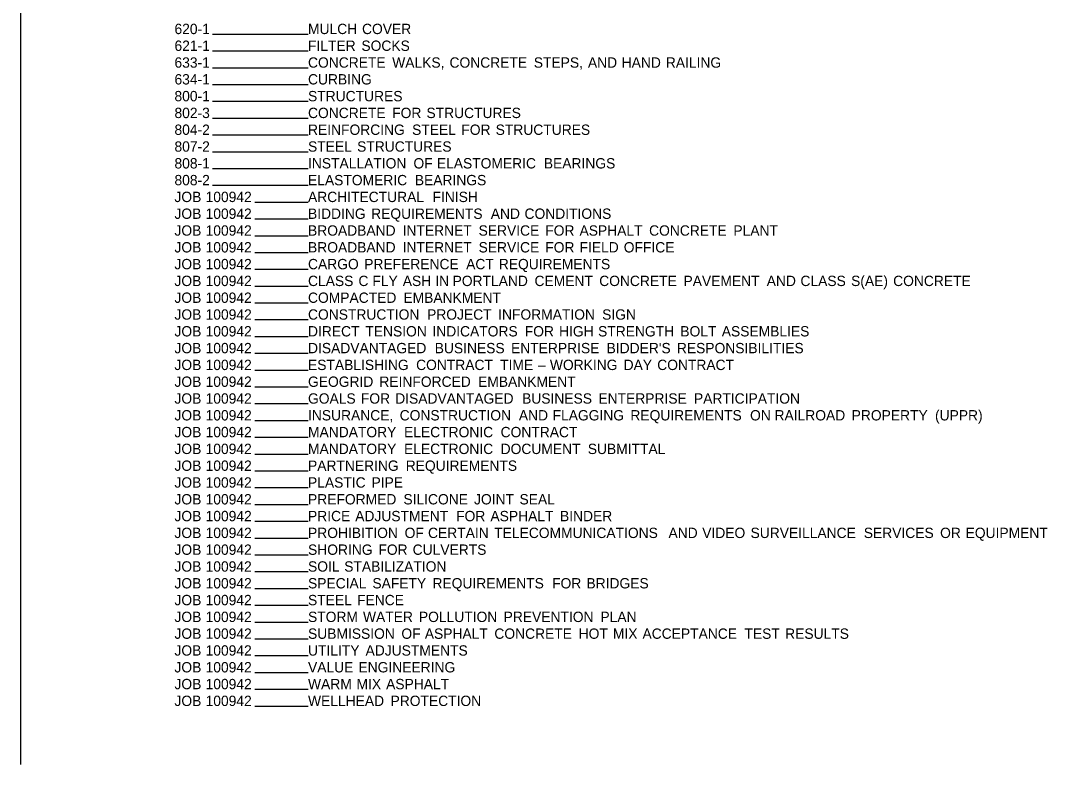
# Model space of a CAD drawing. Extents: x 1.5 to 33, y 0.6 to 21.4.
# Drawn here: x 1.52 to 15.82, y 0.58 to 10.94 of the extents above; entities that cross this region are included whole.
import ezdxf

# ---------------------------------------------------------------- set-up
doc = ezdxf.new("R2010")
doc.units = 0
doc.layers.add('Default', color=7, linetype='Continuous')

msp = doc.modelspace()

# ---------------------------------------------------------------- linework, layer by layer
at = {"layer": 'Default'}
for p, q in [((1.516, 21.423), (1.516, 0.577)), ((4.188, 10.751), (5.52, 10.751)), ((4.188, 10.517), (5.52, 10.517)), ((4.188, 10.283), (5.52, 10.283)), ((4.188, 10.049), (5.52, 10.049)), ((4.188, 9.815), (5.52, 9.815)), ((4.188, 9.581), (5.52, 9.581)), ((4.188, 9.347), (5.52, 9.347)), ((4.188, 9.113), (5.52, 9.113)), ((4.188, 8.879), (5.52, 8.879)), ((4.188, 8.645), (5.52, 8.645)), ((4.78, 8.411), (5.52, 8.411)), ((4.78, 8.177), (5.52, 8.177)), ((4.78, 7.943), (5.52, 7.943)), ((4.78, 7.709), (5.52, 7.709)), ((4.78, 7.475), (5.52, 7.475)), ((4.78, 7.241), (5.52, 7.241)), ((4.78, 7.007), (5.52, 7.007)), ((4.78, 6.773), (5.52, 6.773)), ((4.78, 6.539), (5.52, 6.539)), ((4.78, 6.305), (5.52, 6.305)), ((4.78, 6.071), (5.52, 6.071)), ((4.78, 5.837), (5.52, 5.837)), ((4.78, 5.603), (5.52, 5.603)), ((4.78, 5.369), (5.52, 5.369)), ((4.78, 5.135), (5.52, 5.135)), ((4.78, 4.901), (5.52, 4.901)), ((4.78, 4.667), (5.52, 4.667)), ((4.78, 4.433), (5.52, 4.433)), ((4.78, 4.199), (5.52, 4.199)), ((4.78, 3.965), (5.52, 3.965)), ((4.78, 3.731), (5.52, 3.731)), ((4.78, 3.497), (5.52, 3.497)), ((4.78, 3.263), (5.52, 3.263)), ((4.78, 3.029), (5.52, 3.029)), ((4.78, 2.795), (5.52, 2.795)), ((4.78, 2.561), (5.52, 2.561)), ((4.78, 2.327), (5.52, 2.327)), ((4.78, 2.093), (5.52, 2.093)), ((4.78, 1.859), (5.52, 1.859)), ((4.78, 1.625), (5.52, 1.625)), ((4.78, 1.391), (5.52, 1.391))]:
    msp.add_line(p, q, dxfattribs=at)

# ---------------------------------------------------------------- texts
for s, p in [('620-1', (3.66, 10.751)), ('MULCH', (5.52, 10.751)), (' COVER', (6.219, 10.751)), ('621-1', (3.66, 10.517)), ('FILTER', (5.52, 10.517)), (' SOCKS', (6.21, 10.517)), ('633-1', (3.66, 10.283)), ('CONCRETE', (5.52, 10.283)), (' WALKS,', (6.639, 10.283)), (' CONCRETE', (7.437, 10.283)), (' STEPS,', (8.611, 10.283)), (' AND', (9.365, 10.283)), (' HAND', (9.835, 10.283)), (' RAILING', (10.45, 10.283)), ('634-1', (3.66, 10.049)), ('CURBING', (5.52, 10.049)), ('800-1', (3.66, 9.815)), ('STRUCTURES', (5.52, 9.815)), ('802-3', (3.66, 9.581)), ('CONCRETE', (5.52, 9.581)), (' FOR', (6.639, 9.581)), (' STRUCTURES', (7.116, 9.581)), ('804-2', (3.66, 9.347)), ('REINFORCING', (5.52, 9.347)), (' STEEL', (6.916, 9.347)), (' FOR', (7.602, 9.347)), (' STRUCTURES', (8.08, 9.347)), ('807-2', (3.66, 9.113)), ('STEEL', (5.52, 9.113)), (' STRUCTURES', (6.15, 9.113)), ('808-1', (3.66, 8.879)), ('INSTALLATION', (5.52, 8.879)), (' OF', (6.935, 8.879)), (' ELASTOMERIC', (7.261, 8.879)), (' BEARINGS', (8.751, 8.879)), ('808-2', (3.66, 8.645)), ('ELASTOMERIC', (5.52, 8.645)), (' BEARINGS', (6.954, 8.645)), ('JOB', (3.66, 8.411)), (' 100942', (4.04, 8.411)), ('ARCHITECTURAL', (5.52, 8.411)), (' FINISH', (7.201, 8.411)), ('JOB', (3.66, 8.177)), (' 100942', (4.04, 8.177)), ('BIDDING', (5.52, 8.177)), (' REQUIREMENTS', (6.346, 8.177)), (' AND', (8.012, 8.177)), (' CONDITIONS', (8.482, 8.177)), ('JOB', (3.66, 7.943)), (' 100942', (4.04, 7.943)), ('BROADBAND', (5.52, 7.943)), (' INTERNET', (6.784, 7.943)), (' SERVICE', (7.842, 7.943)), (' FOR', (8.771, 7.943)), (' ASPHALT', (9.248, 7.943)), (' CONCRETE', (10.217, 7.943)), (' PLANT', (11.391, 7.943)), ('JOB', (3.66, 7.709)), (' 100942', (4.04, 7.709)), ('BROADBAND', (5.52, 7.709)), (' INTERNET', (6.784, 7.709)), (' SERVICE', (7.842, 7.709)), (' FOR', (8.771, 7.709)), (' FIELD', (9.248, 7.709)), (' OFFICE', (9.864, 7.709)), ('JOB', (3.66, 7.475)), (' 100942', (4.04, 7.475)), ('CARGO', (5.52, 7.475)), (' PREFERENCE', (6.249, 7.475)), (' ACT', (7.669, 7.475)), (' REQUIREMENTS', (8.124, 7.475)), ('JOB', (3.66, 7.241)), (' 100942', (4.04, 7.241)), ('CLASS', (5.52, 7.241)), (' C', (6.169, 7.241)), (' FLY', (6.363, 7.241)), (' ASH', (6.786, 7.241)), (' IN', (7.239, 7.241)), (' PORTLAND', (7.48, 7.241)), (' CEMENT', (8.621, 7.241)), (' CONCRETE', (9.522, 7.241)), (' PAVEMENT', (10.696, 7.241)), (' AND', (11.855, 7.241)), (' CLASS', (12.325, 7.241)), (' S(AE)', (13.03, 7.241)), (' CONCRETE', (13.616, 7.241)), ('JOB', (3.66, 7.007)), (' 100942', (4.04, 7.007)), ('COMPACTED', (5.52, 7.007)), (' EMBANKMENT', (6.795, 7.007)), ('JOB', (3.66, 6.773)), (' 100942', (4.04, 6.773)), ('CONSTRUCTION', (5.52, 6.773)), (' PROJECT', (7.125, 6.773)), (' INFORMATION', (8.115, 6.773)), (' SIGN', (9.563, 6.773)), ('JOB', (3.66, 6.539)), (' 100942', (4.04, 6.539)), ('DIRECT', (5.52, 6.539)), (' TENSION', (6.265, 6.539)), (' INDICATORS', (7.199, 6.539)), (' FOR', (8.485, 6.539)), (' HIGH', (8.963, 6.539)), (' STRENGTH', (9.506, 6.539)), (' BOLT', (10.652, 6.539)), (' ASSEMBLIES', (11.229, 6.539)), ('JOB', (3.66, 6.305)), (' 100942', (4.04, 6.305)), ('DISADVANTAGED', (5.52, 6.305)), (' BUSINESS', (7.231, 6.305)), (' ENTERPRISE', (8.294, 6.305)), (" BIDDER'S", (9.625, 6.305)), (' RESPONSIBILITIES', (10.604, 6.305)), ('JOB', (3.66, 6.071)), (' 100942', (4.04, 6.071)), ('ESTABLISHING', (5.52, 6.071)), (' CONTRACT', (6.972, 6.071)), (' TIME', (8.142, 6.071)), (' WORKING', (8.835, 6.071)), (' DAY', (9.862, 6.071)), (' CONTRACT', (10.33, 6.071)), ('–', (8.724, 6.071)), ('JOB', (3.66, 5.837)), (' 100942', (4.04, 5.837)), ('GEOGRID', (5.52, 5.837)), (' REINFORCED', (6.46, 5.837)), (' EMBANKMENT', (7.835, 5.837)), ('JOB', (3.66, 5.603)), (' 100942', (4.04, 5.603)), ('GOALS', (5.52, 5.603)), (' FOR', (6.203, 5.603)), (' DISADVANTAGED', (6.681, 5.603)), (' BUSINESS', (8.448, 5.603)), (' ENTERPRISE', (9.511, 5.603)), (' PARTICIPATION', (10.842, 5.603)), ('JOB', (3.66, 5.369)), (' 100942', (4.04, 5.369)), ('INSURANCE,', (5.52, 5.369)), (' CONSTRUCTION', (6.743, 5.369)), (' AND', (8.403, 5.369)), (' FLAGGING', (8.873, 5.369)), (' REQUIREMENTS', (9.956, 5.369)), (' ON', (11.623, 5.369)), (' RAILROAD', (11.964, 5.369)), (' PROPERTY', (13.038, 5.369)), (' (UPPR)', (14.199, 5.369)), ('JOB', (3.66, 5.135)), (' 100942', (4.04, 5.135)), ('MANDATORY', (5.52, 5.135)), (' ELECTRONIC', (6.804, 5.135)), (' CONTRACT', (8.149, 5.135)), ('JOB', (3.66, 4.901)), (' 100942', (4.04, 4.901)), ('MANDATORY', (5.52, 4.901)), (' ELECTRONIC', (6.804, 4.901)), (' DOCUMENT', (8.149, 4.901)), (' SUBMITTAL', (9.363, 4.901)), ('JOB', (3.66, 4.667)), (' 100942', (4.04, 4.667)), ('PARTNERING', (5.52, 4.667)), (' REQUIREMENTS', (6.827, 4.667)), ('JOB', (3.66, 4.433)), (' 100942', (4.04, 4.433)), ('PLASTIC', (5.52, 4.433)), (' PIPE', (6.351, 4.433)), ('JOB', (3.66, 4.199)), (' 100942', (4.04, 4.199)), ('PREFORMED', (5.52, 4.199)), (' SILICONE', (6.795, 4.199)), (' JOINT', (7.779, 4.199)), (' SEAL', (8.412, 4.199)), ('JOB', (3.66, 3.965)), (' 100942', (4.04, 3.965)), ('PRICE', (5.52, 3.965)), (' ADJUSTMENT', (6.124, 3.965)), (' FOR', (7.529, 3.965)), (' ASPHALT', (8.007, 3.965)), (' BINDER', (8.976, 3.965)), ('JOB', (3.66, 3.731)), (' 100942', (4.04, 3.731)), ('PROHIBITION', (5.52, 3.731)), (' OF', (6.812, 3.731)), (' CERTAIN', (7.138, 3.731)), (' TELECOMMUNICATIONS', (8.06, 3.731)), (' AND', (10.487, 3.731)), (' VIDEO', (10.957, 3.731)), (' SURVEILLANCE', (11.63, 3.731)), (' SERVICES', (13.207, 3.731)), (' OR', (14.27, 3.731)), (' EQUIPMENT', (14.625, 3.731)), ('JOB', (3.66, 3.497)), (' 100942', (4.04, 3.497)), ('SHORING', (5.52, 3.497)), (' FOR', (6.447, 3.497)), (' CULVERTS', (6.924, 3.497)), ('JOB', (3.66, 3.263)), (' 100942', (4.04, 3.263)), ('SOIL', (5.52, 3.263)), (' STABILIZATION', (5.971, 3.263)), ('JOB', (3.66, 3.029)), (' 100942', (4.04, 3.029)), ('SPECIAL', (5.52, 3.029)), (' SAFETY', (6.363, 3.029)), (' REQUIREMENTS', (7.2, 3.029)), (' FOR', (8.866, 3.029)), (' BRIDGES', (9.344, 3.029)), ('JOB', (3.66, 2.795)), (' 100942', (4.04, 2.795)), ('STEEL', (5.52, 2.795)), (' FENCE', (6.15, 2.795)), ('JOB', (3.66, 2.561)), (' 100942', (4.04, 2.561)), ('STORM', (5.52, 2.561)), (' WATER', (6.232, 2.561)), (' POLLUTION', (7.011, 2.561)), (' PREVENTION', (8.191, 2.561)), (' PLAN', (9.539, 2.561)), ('JOB', (3.66, 2.327)), (' 100942', (4.04, 2.327)), ('SUBMISSION', (5.52, 2.327)), (' OF', (6.767, 2.327)), (' ASPHALT', (7.093, 2.327)), (' CONCRETE', (8.062, 2.327)), (' HOT', (9.236, 2.327)), (' MIX', (9.713, 2.327)), (' ACCEPTANCE', (10.125, 2.327)), (' TEST', (11.545, 2.327)), (' RESULTS', (12.112, 2.327)), ('JOB', (3.66, 2.093)), (' 100942', (4.04, 2.093)), ('UTILITY', (5.52, 2.093)), (' ADJUSTMENTS', (6.268, 2.093)), ('JOB', (3.66, 1.859)), (' 100942', (4.04, 1.859)), ('VALUE', (5.52, 1.859)), (' ENGINEERING', (6.169, 1.859)), ('JOB', (3.66, 1.625)), (' 100942', (4.04, 1.625)), ('WARM', (5.52, 1.625)), (' MIX', (6.142, 1.625)), (' ASPHALT', (6.554, 1.625)), ('JOB', (3.66, 1.391)), (' 100942', (4.04, 1.391)), ('WELLHEAD', (5.52, 1.391)), (' PROTECTION', (6.616, 1.391))]:
    msp.add_text(s, height=0.144, dxfattribs=at).set_placement(p)

doc.saveas('drawing.dxf')
